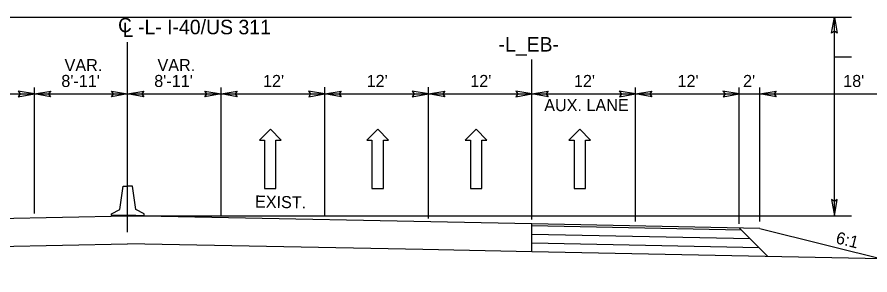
# Model space of a CAD drawing. Extents: x 1726790 to 1728895, y 539219 to 541550.
# Drawn here: x 1727397 to 1727891.1, y 541295.4 to 541445 of the extents above; entities that cross this region are included whole.
import ezdxf

# ---------------------------------------------------------------- set-up
doc = ezdxf.new("R2010")
doc.units = 0
for name, color, linetype in [('Default', 7, 'Continuous'), ('Prop Dimension Text', 7, 'Continuous'), ('Typical Pavement Slope CELL', 7, 'Continuous'), ('Typical Pavement Slope Information CELL', 7, 'Continuous'), ('Typical Text Centerline CELL', 7, 'Continuous')]:
    doc.layers.add(name, color=color, linetype=linetype)

msp = doc.modelspace()

# ---------------------------------------------------------------- linework, layer by layer
at = {"layer": 'Default'}
for p, q in [((1727250.93, 541445), (1727880.5, 541445)), ((1727870.5, 541329.79), (1727870.5, 541445)), ((1727695.28, 541327.57), (1727695.28, 541420.48)), ((1727870.5, 541422.01), (1727880.5, 541422.01)), ((1727407.04, 541331.18), (1727407.04, 541404.16)), ((1727515.13, 541330.19), (1727515.13, 541404.16)), ((1727575.29, 541329.97), (1727575.29, 541404.31)), ((1727635.34, 541328.19), (1727635.34, 541404.28)), ((1727695.28, 541327.57), (1727695.28, 541404.28)), ((1727755.32, 541326.37), (1727755.32, 541404.16)), ((1727815.37, 541326.37), (1727815.37, 541404.16)), ((1727815.37, 541325.17), (1727815.37, 541404.16)), ((1727827.38, 541326.37), (1727827.38, 541404.16)), ((1727346.99, 541400.46), (1727407.04, 541400.46)), ((1727407.04, 541400.46), (1727461.04, 541400.46)), ((1727461.04, 541400.46), (1727515.24, 541400.46)), ((1727515.24, 541400.46), (1727575.29, 541400.46)), ((1727575.29, 541400.46), (1727635.34, 541400.46)), ((1727635.34, 541400.46), (1727695.38, 541400.46)), ((1727695.38, 541400.46), (1727755.43, 541400.46)), ((1727755.43, 541400.46), (1727815.48, 541400.46)), ((1727755.43, 541400.46), (1727815.48, 541400.46)), ((1727815.48, 541400.46), (1727827.38, 541400.46)), ((1727827.38, 541400.46), (1727935.46, 541400.46)), ((1727543.74, 541379.98), (1727537.34, 541373.68)), ((1727549.94, 541373.68), (1727543.74, 541379.98)), ((1727606, 541379.98), (1727599.6, 541373.68)), ((1727612.2, 541373.68), (1727606, 541379.98)), ((1727663, 541379.98), (1727656.6, 541373.68)), ((1727669.2, 541373.68), (1727663, 541379.98)), ((1727723.05, 541379.98), (1727716.65, 541373.68)), ((1727729.25, 541373.68), (1727723.05, 541379.98)), ((1727537.34, 541373.68), (1727540.34, 541373.68)), ((1727540.34, 541373.68), (1727540.34, 541345.68)), ((1727546.94, 541345.68), (1727546.94, 541373.68)), ((1727546.94, 541373.68), (1727549.94, 541373.68)), ((1727599.6, 541373.68), (1727602.6, 541373.68)), ((1727602.6, 541373.68), (1727602.6, 541345.68)), ((1727609.2, 541345.68), (1727609.2, 541373.68)), ((1727609.2, 541373.68), (1727612.2, 541373.68)), ((1727656.6, 541373.68), (1727659.6, 541373.68)), ((1727659.6, 541373.68), (1727659.6, 541345.68)), ((1727666.2, 541345.68), (1727666.2, 541373.68)), ((1727666.2, 541373.68), (1727669.2, 541373.68)), ((1727716.65, 541373.68), (1727719.65, 541373.68)), ((1727719.65, 541373.68), (1727719.65, 541345.68)), ((1727726.25, 541345.68), (1727726.25, 541373.68)), ((1727726.25, 541373.68), (1727729.25, 541373.68)), ((1727540.34, 541345.68), (1727546.94, 541345.68)), ((1727602.6, 541345.68), (1727609.2, 541345.68)), ((1727659.6, 541345.68), (1727666.2, 541345.68)), ((1727719.65, 541345.68), (1727726.25, 541345.68)), ((1727461.04, 541329.79), (1727880.5, 541329.79))]:
    msp.add_line(p, q, dxfattribs=at)
for points in [[(1727868.89, 541435.66), (1727870.5, 541445.04), (1727872.17, 541435.61), (1727870.5, 541436.8)], [(1727397.66, 541398.85), (1727407.04, 541400.46), (1727397.61, 541402.13), (1727398.8, 541400.46)], [(1727416.42, 541398.85), (1727407.04, 541400.46), (1727416.47, 541402.13), (1727415.27, 541400.46)], [(1727451.66, 541402.08), (1727461.04, 541400.46), (1727451.61, 541398.8), (1727452.8, 541400.46)], [(1727470.41, 541398.85), (1727461.04, 541400.46), (1727470.47, 541402.13), (1727469.27, 541400.46)], [(1727505.76, 541402.08), (1727515.13, 541400.46), (1727505.7, 541398.79), (1727506.9, 541400.46)], [(1727524.51, 541398.85), (1727515.13, 541400.46), (1727524.56, 541402.13), (1727523.37, 541400.46)], [(1727565.91, 541398.85), (1727575.29, 541400.46), (1727565.86, 541402.13), (1727567.06, 541400.46)], [(1727584.67, 541398.85), (1727575.29, 541400.46), (1727584.72, 541402.13), (1727583.52, 541400.46)], [(1727625.96, 541398.85), (1727635.34, 541400.46), (1727625.91, 541402.13), (1727627.11, 541400.46)], [(1727644.72, 541398.85), (1727635.34, 541400.46), (1727644.77, 541402.13), (1727643.57, 541400.46)], [(1727685.9, 541398.85), (1727695.28, 541400.46), (1727685.85, 541402.13), (1727687.04, 541400.46)], [(1727704.65, 541398.85), (1727695.28, 541400.46), (1727704.71, 541402.13), (1727703.51, 541400.46)], [(1727745.94, 541398.85), (1727755.32, 541400.46), (1727745.89, 541402.13), (1727747.09, 541400.46)], [(1727764.7, 541398.85), (1727755.32, 541400.46), (1727764.75, 541402.13), (1727763.56, 541400.46)], [(1727805.99, 541398.85), (1727815.37, 541400.46), (1727805.94, 541402.13), (1727807.14, 541400.46)], [(1727836.76, 541398.85), (1727827.38, 541400.46), (1727836.81, 541402.13), (1727835.61, 541400.46)], [(1727868.88, 541339.17), (1727870.5, 541329.79), (1727872.17, 541339.22), (1727870.5, 541338.02)]]:
    msp.add_lwpolyline(points, close=True, dxfattribs=at)
at = {"layer": 'Typical Pavement Slope CELL'}
for p, q in [((1727456.45, 541333.39), (1727458.42, 541346.9)), ((1727458.42, 541346.9), (1727461.14, 541346.9)), ((1727463.86, 541346.9), (1727461.14, 541346.9)), ((1727465.83, 541333.39), (1727463.86, 541346.9)), ((1727226.79, 541325.1), (1727461.04, 541329.79)), ((1727695.28, 541325.1), (1727461.04, 541329.79)), ((1727695.28, 541308.86), (1727695.28, 541325.1)), ((1727827.38, 541322.46), (1727695.28, 541325.1)), ((1727816.63, 541321.44), (1727695.28, 541323.87)), ((1727821.73, 541316.34), (1727695.28, 541318.87)), ((1727815.37, 541322.7), (1727831.94, 541306.13)), ((1727827.39, 541322.46), (1727935.46, 541295.44)), ((1727631.98, 541310.13), (1727461.04, 541313.55)), ((1727826.84, 541311.24), (1727695.28, 541313.87)), ((1727226.79, 541308.85), (1727461.04, 541313.53)), ((1727695.28, 541308.86), (1727631.98, 541310.13)), ((1727898, 541304.81), (1727695.28, 541308.86))]:
    msp.add_line(p, q, dxfattribs=at)
for points in [[(1727465.68, 541329.87), (1727451.73, 541329.87), (1727451.73, 541330.95), (1727456.45, 541333.39)], [(1727456.59, 541329.87), (1727470.55, 541329.87), (1727470.55, 541330.95), (1727465.83, 541333.39)]]:
    msp.add_lwpolyline(points, dxfattribs=at)
at = {"layer": 'Typical Text Centerline CELL'}
msp.add_line((1727461.04, 541320.33), (1727461.04, 541430.42), dxfattribs=at)

# ---------------------------------------------------------------- texts
at = {"layer": 'Prop Dimension Text'}
msp.add_text("18'", height=7.005, dxfattribs=at).set_placement((1727875.61, 541404.46))
msp.add_text('6:1', height=7.005, rotation=345.9638, dxfattribs=at).set_placement((1727870.86, 541313.91))
at = {"layer": 'Typical Pavement Slope Information CELL'}
for s, p in [('VAR.', (1727424.49, 541413.65)), ('VAR.', (1727478.32, 541413.65)), ("8'-11'", (1727422.61, 541404.47)), ("8'-11'", (1727476.44, 541404.46)), ("12'", (1727539.45, 541404.46)), ("12'", (1727599.5, 541404.46)), ("12'", (1727659.55, 541404.46)), ("12'", (1727719.6, 541404.46)), ("12'", (1727779.64, 541404.46)), ("2'", (1727817.55, 541404.46)), ('AUX. LANE', (1727702.38, 541390.45))]:
    msp.add_text(s, height=7.005, dxfattribs=at).set_placement(p)
msp.add_text('EXIST.', height=7.005, rotation=358.8543, dxfattribs=at).set_placement((1727534.75, 541334.57))
at = {"layer": 'Typical Text Centerline CELL'}
for s, height, rotation, p in [('C', 8.2, 0.0443, (1727455.51, 541436.27)), ('-L- I-40/US 311', 8.4214, 359.9417, (1727467.01, 541435.08)), ('L', 8.21, 359.9912, (1727458.24, 541433.48))]:
    msp.add_text(s, height=height, rotation=rotation, dxfattribs=at).set_placement(p)
msp.add_text('-L_EB-', height=8.421, dxfattribs=at).set_placement((1727675.91, 541425.02))

doc.saveas('drawing.dxf')
